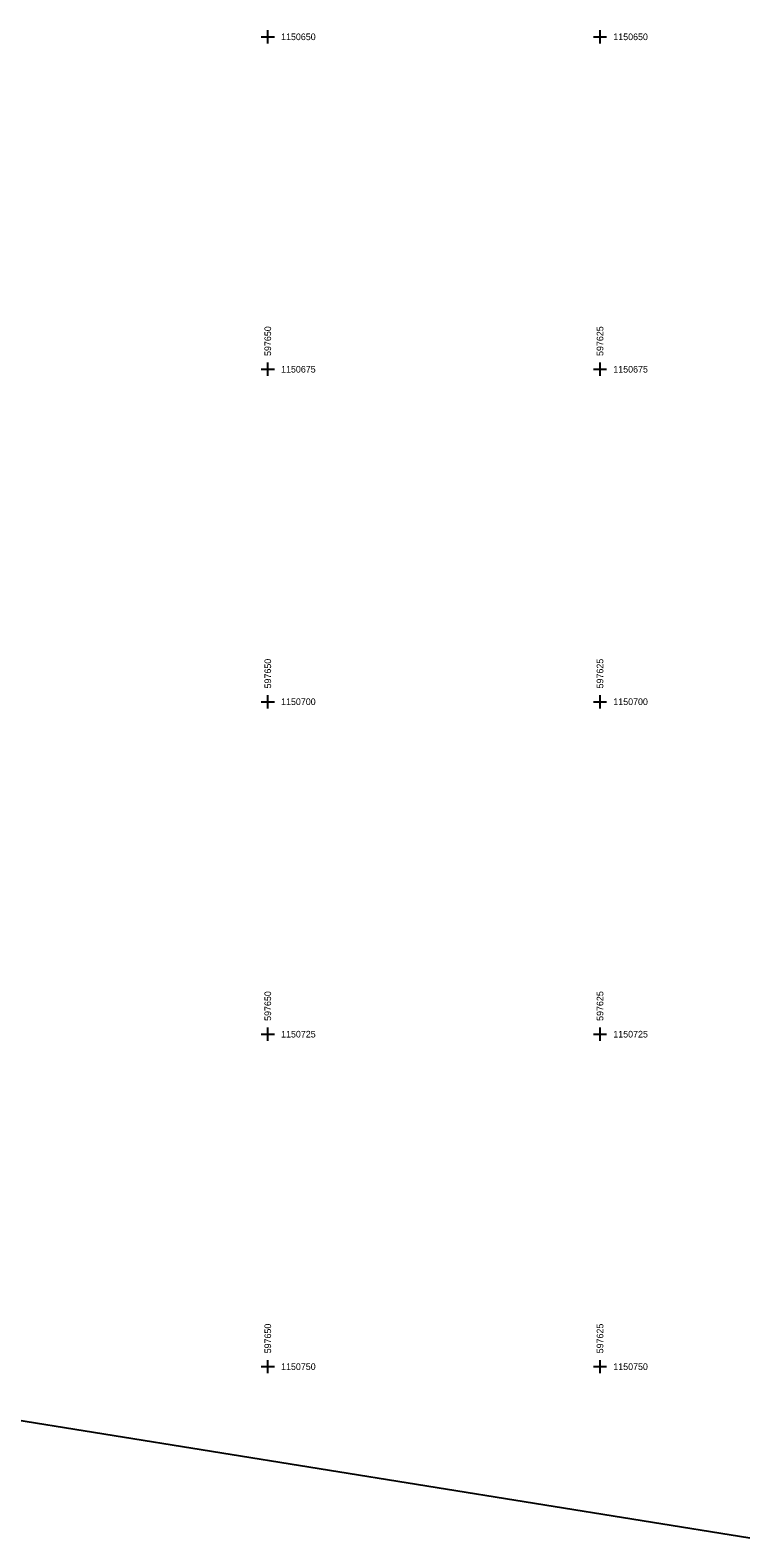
# Model space of a CAD drawing. Extents: x -600096 to -597522, y -1151695 to -1149849.
# Drawn here: x -597667.9 to -597613.7, y -1150762.9 to -1150649.5 of the extents above; entities that cross this region are included whole.
import ezdxf

# ---------------------------------------------------------------- set-up
doc = ezdxf.new("R2010")
doc.units = 0
doc.layers.add('Ram03', color=7, linetype='Continuous')
doc.layers.add('Vrstva 5', color=7, linetype='Continuous')

msp = doc.modelspace()

# ---------------------------------------------------------------- linework, layer by layer
at = {"layer": 'Ram03'}
msp.add_line((-597760.34, -1150739.3), (-597613.72, -1150762.87), dxfattribs=at)
at = {"layer": 'Vrstva 5'}
for points in [[(-597650.5, -1150650), (-597650, -1150650), (-597649.5, -1150650)], [(-597650, -1150650.5), (-597650, -1150650), (-597650, -1150649.5)], [(-597625.5, -1150650), (-597625, -1150650), (-597624.5, -1150650)], [(-597625, -1150650.5), (-597625, -1150650), (-597625, -1150649.5)], [(-597650.5, -1150675), (-597650, -1150675), (-597649.5, -1150675)], [(-597650, -1150675.5), (-597650, -1150675), (-597650, -1150674.5)], [(-597625.5, -1150675), (-597625, -1150675), (-597624.5, -1150675)], [(-597625, -1150675.5), (-597625, -1150675), (-597625, -1150674.5)], [(-597650.5, -1150700), (-597650, -1150700), (-597649.5, -1150700)], [(-597650, -1150700.5), (-597650, -1150700), (-597650, -1150699.5)], [(-597625.5, -1150700), (-597625, -1150700), (-597624.5, -1150700)], [(-597625, -1150700.5), (-597625, -1150700), (-597625, -1150699.5)], [(-597650.5, -1150725), (-597650, -1150725), (-597649.5, -1150725)], [(-597650, -1150725.5), (-597650, -1150725), (-597650, -1150724.5)], [(-597625.5, -1150725), (-597625, -1150725), (-597624.5, -1150725)], [(-597625, -1150725.5), (-597625, -1150725), (-597625, -1150724.5)], [(-597650.5, -1150750), (-597650, -1150750), (-597649.5, -1150750)], [(-597650, -1150750.5), (-597650, -1150750), (-597650, -1150749.5)], [(-597625.5, -1150750), (-597625, -1150750), (-597624.5, -1150750)], [(-597625, -1150750.5), (-597625, -1150750), (-597625, -1150749.5)]]:
    msp.add_lwpolyline(points, dxfattribs=at)

# ---------------------------------------------------------------- texts
for s, p in [('1150650', (-597649, -1150650.25)), ('1150650', (-597624, -1150650.25)), ('1150675', (-597649, -1150675.25)), ('1150675', (-597624, -1150675.25)), ('1150700', (-597649, -1150700.25)), ('1150700', (-597624, -1150700.25)), ('1150725', (-597649, -1150725.25)), ('1150725', (-597624, -1150725.25)), ('1150750', (-597649, -1150750.25)), ('1150750', (-597624, -1150750.25))]:
    msp.add_text(s, height=0.5, dxfattribs=at).set_placement(p)
for s, p in [('597650', (-597649.75, -1150674)), ('597625', (-597624.75, -1150674)), ('597650', (-597649.75, -1150699)), ('597625', (-597624.75, -1150699)), ('597650', (-597649.75, -1150724)), ('597625', (-597624.75, -1150724)), ('597650', (-597649.75, -1150749)), ('597625', (-597624.75, -1150749))]:
    msp.add_text(s, height=0.5, rotation=90, dxfattribs=at).set_placement(p)

doc.saveas('drawing.dxf')
